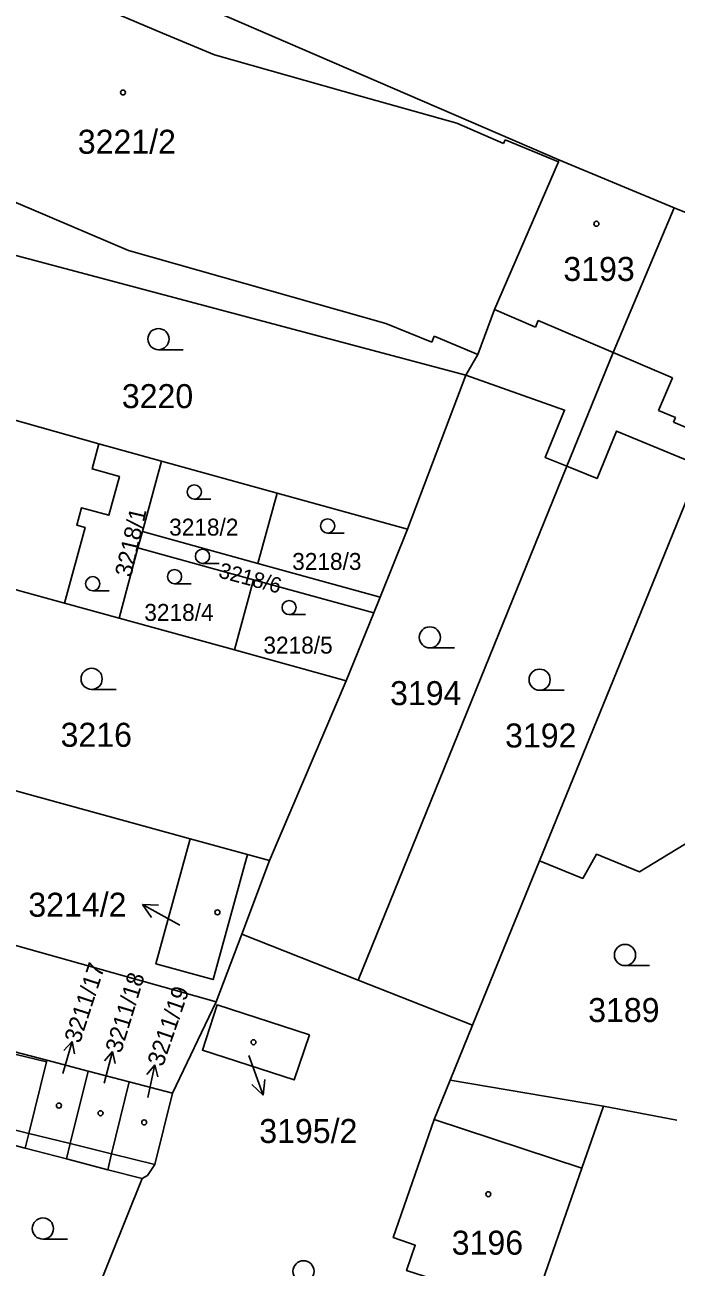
# Model space of a CAD drawing. Extents: x -756746 to -753363, y -1166406 to -1161727.
# Drawn here: x -755576.1 to -755529.9, y -1165303.9 to -1165215.9 of the extents above; entities that cross this region are included whole.
import ezdxf

# ---------------------------------------------------------------- set-up
doc = ezdxf.new("R2010")
doc.units = 0
for name, color, linetype in [('Hranice parcel', 7, 'Continuous'), ('Parcelní čísla', 7, 'Continuous'), ('Pop  PČ popisy', 7, 'Continuous'), ('Vnitřní kresba', 7, 'Continuous'), ('Značky budov', 7, 'Continuous'), ('Značky kultur', 7, 'Continuous')]:
    doc.layers.add(name, color=color, linetype=linetype)

msp = doc.modelspace()

# ---------------------------------------------------------------- linework, layer by layer
at = {"layer": 'Hranice parcel'}
for p, q in [((-755530.07, -1165228.87), (-755538.25, -1165225.49)), ((-755522.15, -1165232.14), (-755530.07, -1165228.87)), ((-755544.83, -1165240.74), (-755548.97, -1165251.65)), ((-755570.84, -1165245.61), (-755566.41, -1165246.83)), ((-755567.76, -1165251.81), (-755566.41, -1165246.83)), ((-755566.41, -1165246.83), (-755558.22, -1165249.1)), ((-755537.68, -1165247.19), (-755552.47, -1165283.59)), ((-755559.57, -1165254.07), (-755558.22, -1165249.1)), ((-755558.22, -1165249.1), (-755548.97, -1165251.65)), ((-755568.08, -1165252.97), (-755567.76, -1165251.81)), ((-755567.76, -1165251.81), (-755559.57, -1165254.07)), ((-755548.97, -1165251.65), (-755550.92, -1165256.46)), ((-755569.42, -1165257.94), (-755568.08, -1165252.97)), ((-755559.88, -1165255.23), (-755568.08, -1165252.97)), ((-755573.28, -1165256.88), (-755585.04, -1165253.66)), ((-755559.57, -1165254.07), (-755550.92, -1165256.46)), ((-755561.23, -1165260.2), (-755559.88, -1165255.23)), ((-755551.37, -1165257.57), (-755559.88, -1165255.23)), ((-755550.92, -1165256.46), (-755551.37, -1165257.57)), ((-755569.42, -1165257.94), (-755573.28, -1165256.88)), ((-755561.23, -1165260.2), (-755569.42, -1165257.94)), ((-755551.37, -1165257.57), (-755553.32, -1165262.38)), ((-755553.32, -1165262.38), (-755561.23, -1165260.2)), ((-755553.32, -1165262.38), (-755558.75, -1165275.12)), ((-755560.32, -1165274.69), (-755564.38, -1165273.57)), ((-755558.75, -1165275.12), (-755560.72, -1165280.34)), ((-755558.75, -1165275.12), (-755560.32, -1165274.69)), ((-755539.61, -1165275.14), (-755544.36, -1165286.79)), ((-755562.53, -1165285.14), (-755592.52, -1165276.72)), ((-755560.72, -1165280.34), (-755562.53, -1165285.14)), ((-755560.72, -1165280.34), (-755552.47, -1165283.59)), ((-755552.47, -1165283.59), (-755544.36, -1165286.79)), ((-755562.53, -1165285.14), (-755565.62, -1165291.59)), ((-755544.36, -1165286.79), (-755545.94, -1165290.68)), ((-755577.45, -1165288.51), (-755574.53, -1165289.27)), ((-755574.53, -1165289.27), (-755571.61, -1165290.03)), ((-755571.61, -1165290.03), (-755568.69, -1165290.79)), ((-755568.69, -1165290.79), (-755565.62, -1165291.59)), ((-755545.94, -1165290.68), (-755535.09, -1165292.52)), ((-755529.88, -1165293.5), (-755535.09, -1165292.52)), ((-755576.07, -1165295.5), (-755578.99, -1165294.75)), ((-755573.15, -1165296.26), (-755576.07, -1165295.5)), ((-755570.22, -1165297.02), (-755573.15, -1165296.26)), ((-755567.78, -1165297.65), (-755570.22, -1165297.02)), ((-755567.78, -1165297.65), (-755572.07, -1165308.31))]:
    msp.add_line(p, q, dxfattribs=at)
for points in [[(-755600.49, -1165201.25), (-755598.23, -1165202.11), (-755598.09, -1165201.75), (-755595.43, -1165202.48), (-755595.43, -1165202.85), (-755578.93, -1165207.9), (-755538.25, -1165225.49)], [(-755538.25, -1165225.49), (-755538.28, -1165225.63), (-755542.82, -1165236.09), (-755543.98, -1165239.26), (-755544.83, -1165240.74)], [(-755530.07, -1165228.87), (-755534.4, -1165239.13), (-755537.68, -1165247.19)], [(-755544.83, -1165240.74), (-755578.09, -1165231.91), (-755582.33, -1165230.55), (-755583.28, -1165230.29)], [(-755544.83, -1165240.74), (-755537.84, -1165243.21), (-755539.21, -1165246.57), (-755537.68, -1165247.19)], [(-755570.84, -1165245.61), (-755584.51, -1165241.75), (-755586.31, -1165241.27)], [(-755537.68, -1165247.19), (-755535.54, -1165248.06), (-755534.17, -1165244.7), (-755528.22, -1165247.15)], [(-755573.28, -1165256.88), (-755571.83, -1165251.53), (-755572.41, -1165251.37), (-755572.07, -1165250.13), (-755570.13, -1165250.66), (-755569.39, -1165247.91), (-755571.33, -1165247.38), (-755570.84, -1165245.61)], [(-755528.22, -1165247.15), (-755532.71, -1165258.18), (-755539.61, -1165275.14)], [(-755564.38, -1165273.57), (-755578.38, -1165269.73), (-755588.67, -1165266.94)], [(-755526.27, -1165284.73), (-755528.17, -1165283.95), (-755524.8, -1165275.6), (-755523.42, -1165270.38), (-755532.53, -1165275.91), (-755535.59, -1165274.67), (-755536.55, -1165276.38), (-755539.61, -1165275.14)], [(-755560.32, -1165274.69), (-755562.75, -1165283.55), (-755566.81, -1165282.43), (-755564.38, -1165273.57)], [(-755555.93, -1165287.47), (-755557, -1165290.66), (-755563.51, -1165288.55), (-755562.47, -1165285.34), (-755555.93, -1165287.47)], [(-755576.07, -1165295.5), (-755575.81, -1165294.45), (-755574.56, -1165289.38), (-755574.53, -1165289.27)], [(-755573.15, -1165296.26), (-755572.88, -1165295.17), (-755571.61, -1165290.03)], [(-755570.22, -1165297.02), (-755569.95, -1165295.9), (-755568.69, -1165290.79)], [(-755540.13, -1165307.02), (-755549.04, -1165304.17), (-755548.43, -1165302.37), (-755549.99, -1165301.83), (-755547.08, -1165293.46), (-755545.94, -1165290.68)], [(-755565.62, -1165291.59), (-755566.87, -1165296.66), (-755567.39, -1165297.42), (-755567.78, -1165297.65)], [(-755535.09, -1165292.52), (-755536.62, -1165296.91), (-755540.13, -1165307.02)]]:
    msp.add_lwpolyline(points, dxfattribs=at)
at = {"layer": 'Pop  PČ popisy'}
for p, q in [((-755565.12, -1165279.69), (-755567.745, -1165278.235)), ((-755567.745, -1165278.235), (-755566.626, -1165278.283)), ((-755567.745, -1165278.235), (-755567.112, -1165279.159)), ((-755573.39, -1165290.21), (-755572.737, -1165287.931)), ((-755572.737, -1165287.931), (-755573.335, -1165288.583)), ((-755572.737, -1165287.931), (-755572.574, -1165288.801)), ((-755570.47, -1165290.89), (-755569.872, -1165288.658)), ((-755569.872, -1165288.658), (-755570.444, -1165289.303)), ((-755569.872, -1165288.658), (-755569.699, -1165289.503)), ((-755560.23, -1165288.93), (-755559.204, -1165291.75)), ((-755566.887, -1165289.591), (-755567.439, -1165290.283)), ((-755567.38, -1165291.91), (-755566.887, -1165289.591)), ((-755566.887, -1165289.591), (-755566.665, -1165290.447)), ((-755559.204, -1165291.75), (-755560.017, -1165290.98)), ((-755559.204, -1165291.75), (-755559.076, -1165290.638))]:
    msp.add_line(p, q, dxfattribs=at)
at = {"layer": 'Vnitřní kresba'}
for p, q in [((-755571.7, -1165214.24), (-755566.33, -1165216.5)), ((-755566.33, -1165216.5), (-755562.66, -1165218.04)), ((-755562.66, -1165218.04), (-755552.31, -1165220.96)), ((-755552.31, -1165220.96), (-755545.48, -1165222.89)), ((-755545.48, -1165222.89), (-755542.17, -1165224.32)), ((-755542.17, -1165224.32), (-755542.06, -1165224.07)), ((-755542.06, -1165224.07), (-755538.28, -1165225.63)), ((-755575.62, -1165228.98), (-755580.46, -1165226.95)), ((-755568.74, -1165231.91), (-755575.62, -1165228.98)), ((-755550.52, -1165237.07), (-755568.74, -1165231.91)), ((-755542.82, -1165236.09), (-755539.91, -1165237.33)), ((-755547.25, -1165238.39), (-755550.52, -1165237.07)), ((-755539.91, -1165237.33), (-755539.72, -1165236.87)), ((-755539.72, -1165236.87), (-755534.4, -1165239.13)), ((-755547.08, -1165237.98), (-755547.25, -1165238.39)), ((-755543.98, -1165239.26), (-755547.08, -1165237.98)), ((-755534.4, -1165239.13), (-755530.2, -1165240.92)), ((-755530.2, -1165240.92), (-755531.18, -1165243.23)), ((-755531.18, -1165243.23), (-755529.99, -1165243.73)), ((-755529.99, -1165243.73), (-755530.13, -1165244.06)), ((-755530.13, -1165244.06), (-755527.42, -1165245.21)), ((-755574.56, -1165289.38), (-755577.49, -1165288.66)), ((-755547.08, -1165293.46), (-755536.62, -1165296.91)), ((-755575.81, -1165294.45), (-755578.74, -1165293.73)), ((-755572.88, -1165295.17), (-755575.81, -1165294.45)), ((-755569.95, -1165295.9), (-755572.88, -1165295.17)), ((-755566.87, -1165296.66), (-755569.95, -1165295.9))]:
    msp.add_line(p, q, dxfattribs=at)
at = {"layer": 'Značky budov'}
for centre in [(-755569.137, -1165220.709), (-755535.587, -1165230.009), (-755562.447, -1165278.789), (-755559.887, -1165287.989), (-755573.677, -1165292.479), (-755570.727, -1165293.019), (-755567.637, -1165293.669), (-755543.247, -1165298.759)]:
    msp.add_circle(centre, 0.175, dxfattribs=at)
at = {"layer": 'Značky kultur'}
for p, q in [((-755566.623, -1165238.93), (-755564.873, -1165238.93)), ((-755564.085, -1165249.51), (-755562.913, -1165249.51)), ((-755554.635, -1165251.92), (-755553.463, -1165251.92)), ((-755563.505, -1165254.07), (-755562.333, -1165254.07)), ((-755565.485, -1165255.51), (-755564.313, -1165255.51)), ((-755571.285, -1165256.01), (-755570.113, -1165256.01)), ((-755557.365, -1165257.7), (-755556.193, -1165257.7)), ((-755547.393, -1165260.06), (-755545.643, -1165260.06)), ((-755571.363, -1165263), (-755569.613, -1165263)), ((-755539.613, -1165263.06), (-755537.863, -1165263.06)), ((-755533.563, -1165282.56), (-755531.813, -1165282.56)), ((-755574.813, -1165301.94), (-755573.063, -1165301.94))]:
    msp.add_line(p, q, dxfattribs=at)
for centre, radius in [((-755566.623, -1165238.18), 0.75), ((-755564.085, -1165249.007), 0.502), ((-755554.635, -1165251.417), 0.502), ((-755563.505, -1165253.567), 0.502), ((-755565.485, -1165255.007), 0.502), ((-755571.285, -1165255.507), 0.502), ((-755557.365, -1165257.197), 0.502), ((-755547.393, -1165259.31), 0.75), ((-755571.363, -1165262.25), 0.75), ((-755539.613, -1165262.31), 0.75), ((-755533.563, -1165281.81), 0.75), ((-755574.813, -1165301.19), 0.75), ((-755556.343, -1165304.22), 0.75)]:
    msp.add_circle(centre, radius, dxfattribs=at)

# ---------------------------------------------------------------- texts
at = {"layer": 'Parcelní čísla'}
for s, height, p in [('3221/2', 1.7, (-755572.34, -1165225.05)), ('3193', 1.7, (-755537.93, -1165234.06)), ('3220', 1.7, (-755569.22, -1165243.07)), ('3218/2', 1.2, (-755565.866, -1165252.1)), ('3218/3', 1.2, (-755557.146, -1165254.53)), ('3218/4', 1.2, (-755567.626, -1165258.14)), ('3218/5', 1.2, (-755559.186, -1165260.46)), ('3194', 1.7, (-755550.21, -1165264.11)), ('3216', 1.7, (-755573.56, -1165267.06)), ('3192', 1.7, (-755542.06, -1165267.11)), ('3214/2', 1.7, (-755575.845, -1165279.1)), ('3189', 1.7, (-755536.17, -1165286.56)), ('3195/2', 1.7, (-755559.48, -1165295.128)), ('3196', 1.7, (-755545.84, -1165303.04))]:
    msp.add_text(s, height=height, dxfattribs=at).set_placement(p)
for s, height, rotation, p in [('3218/1', 1.2, 77, (-755568.562, -1165255.1)), ('3218/6', 1.1, 345, (-755562.429, -1165255.05)), ('3211/17', 1.2, 72, (-755572.189, -1165288.125)), ('3211/18', 1.2, 73, (-755569.276, -1165288.825)), ('3211/19', 1.2, 71, (-755566.312, -1165289.775))]:
    msp.add_text(s, height=height, rotation=rotation, dxfattribs=at).set_placement(p)

doc.saveas('drawing.dxf')
